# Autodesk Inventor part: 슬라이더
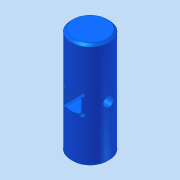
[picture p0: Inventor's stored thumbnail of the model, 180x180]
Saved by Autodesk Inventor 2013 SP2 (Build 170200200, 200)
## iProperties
Company: 한국ATC센터
Created: 2015-04
Part Number: 슬라이더
Document SubType Name: Modeling
Designer: KYOUNG IL JANG
Density: 7.85 g/cm^3
Material: 강
Author: KYOUNG IL JANG
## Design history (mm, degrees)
sketch "스케치1"
  geometry: C1 r 9 at (0, 0); 1 further point
  constraints: 1 centre point, 1 coincident
  dimensions: "d0" = 18 diameter of C1
extrude "돌출1" new body sketch "스케치1" stored distance "d1" = 50; taper "d2" = 0 deg
node "작업 평면1"
sketch "스케치3"
  geometry: L1 (4, 25)-(-4, 25); L2 (-4, 25)-(-4, -25); L3 (-4, -25)-(4, -25); L4 (4, -25)-(4, 25); 3 further points
  constraints: 8 end point, 2 midpoint, 2 parallel, 1 horizontal, 1 horizontal alignment, 1 perpendicular, 1 vertical alignment
  dimensions: "d5" = 8 distance of L1.start L1.end; "d6" = 50 distance of L1.end L2.end
extrude "돌출3" cut sketch "스케치3" stored distance "d7" = 8; taper "d8" = 0 deg
sketch "스케치4"
  geometry: 5 further points
hole "구멍1" sketch "스케치4" at (4, 4), (-4, 4), (-4, -4), (4, -4) diameter "d9" = 2; stored, may be unused: countersink angle "d13" = 90 deg, drill point angle "d15" = 118 deg; dims "d10" = 6, "d11" = 4, "d12" = 2, "d14" = 8
node "작업 평면2"
sketch "스케치5"
  geometry: 1 further point
hole "구멍2" sketch "스케치5" at (0, 0) diameter "d16" = 5; stored, may be unused: countersink angle "d20" = 90 deg, drill point angle "d22" = 118 deg; dims "d17" = 6, "d18" = 4, "d19" = 2, "d21" = 8
chamfer "모따기1" distance "d23" = 1; stored, may be unused: second distance "d24" = 2, angle "d25" = 45 deg
node "솔리드1"
mirror "대칭1"
